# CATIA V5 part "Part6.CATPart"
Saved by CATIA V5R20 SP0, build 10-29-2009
Part number: Part6
Bounding box of the stored display mesh (mm): x 0 to 10, y 144.623 to 168.623, z -11.99 to 361.99
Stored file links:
  C:\Users\Orange\Desktop\Assembly Design-3\Part6.CATPart
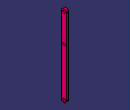
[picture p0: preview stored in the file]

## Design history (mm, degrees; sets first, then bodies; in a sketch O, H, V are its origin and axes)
Body1 (main body)
  Sketch1 on yz-plane, origin (0, 0, 0), H (0, 1, 0), V (0, 0, 1)
    construction line L1 (156.6234, 0) -> (156.6234, 350)
    point P1 (156.6234, 0)
    line L2 (144.6234, 0) -> (144.6234, 350)
    line L3 (168.6234, 350) -> (168.6234, 0)
    arc A1 centre (156.6234, 350) radius 12 from (144.6234, 350) to (168.6234, 350) cw
    arc A2 centre (156.6234, 0) radius 12 from (168.6234, 0) to (144.6234, 0) cw
    circle A3 centre (156.6234, 0) radius 6
    circle A4 centre (156.6234, 220) radius 6
    circle A5 centre (156.6234, 350) radius 6
    length L1 = 350
    distance L1 L2 = 12
    radius A3 = 6
    radius A5 = 6
    coincidence: P1 H
    vertical: L1 V
    tangency: A1 L2, A2 L2, A1 L3, A2 L3
  Pad1: profile Sketch1, direction (1, 0, 0), length 10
